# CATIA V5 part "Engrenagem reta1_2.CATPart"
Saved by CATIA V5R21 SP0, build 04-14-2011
Part number: Engrenagem reta1_2
Definition: Engrenagem reta1_2
Nomenclature: Engrenagem reta15
Source: Unknown
Bounding box of the stored display mesh (mm): x -0.99 to 0.99, y -0.989 to 0.989, z 0 to 2.5
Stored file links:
  C:\Users\beatr\OneDrive\Documents\UNB\2026_1\Pi1\Componentes eletronicos\Engrenagem reta1_2.CATPart
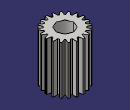
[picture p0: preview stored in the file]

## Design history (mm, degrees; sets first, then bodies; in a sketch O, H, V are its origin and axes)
Body1 "Solid1" (main body)
  Solid1: solid without history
